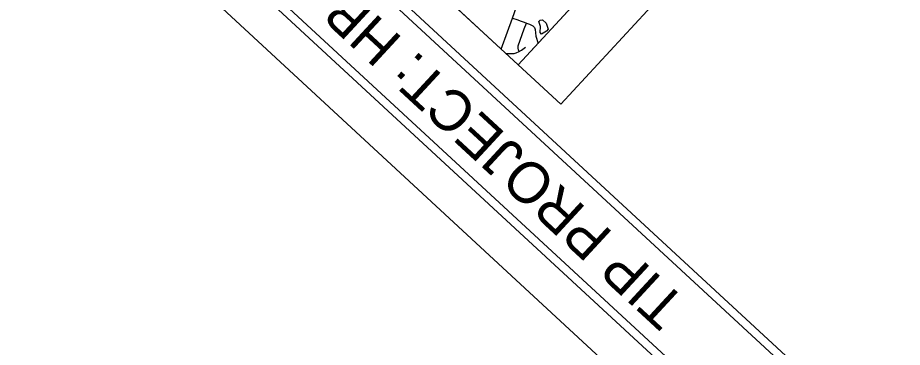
# Model space of a CAD drawing. Extents: x 1766669 to 1770980, y 998119 to 1002502.
# Drawn here: x 1766669 to 1767853, y 999053 to 999494 of the extents above; entities that cross this region are included whole.
import ezdxf

# ---------------------------------------------------------------- set-up
doc = ezdxf.new("R2010")
doc.units = 0
for name, color, linetype in [('Default', 7, 'Continuous'), ('Default Symbol CELL', 7, 'Continuous'), ('Exist DTM Breakline', 7, 'Continuous'), ('Exist DTM Crownline', 7, 'Continuous'), ('Exist Roads Soil', 7, 'Continuous'), ('PH Exist DTM Breakline', 7, 'Continuous')]:
    doc.layers.add(name, color=color, linetype=linetype)

msp = doc.modelspace()

# ---------------------------------------------------------------- linework, layer by layer
at = {"layer": 'Default'}
msp.add_lwpolyline([(1766911.4, 999825.8), (1767342.4, 1000292), (1767769.6, 999897.2), (1767338.6, 999431)], close=True, dxfattribs=at)
at = {"layer": 'Default Symbol CELL'}
for p, q in [((1767768.8, 999896.4), (1767338.6, 999431)), ((1767826.5, 999844.5), (1767395.6, 999378.3)), ((1768487.4, 998295.9), (1766841.5, 999817.2)), ((1768196.4, 998579.9), (1766849, 999825.3)), ((1767395.6, 999378.3), (1766911.4, 999825.8))]:
    msp.add_line(p, q, dxfattribs=at)
for points in [[(1766758.9, 999744.1), (1768420.8, 998207.8)], [(1766758.9, 999744), (1768420.9, 998207.7)], [(1766758.9, 999744), (1768420.9, 998207.7)], [(1766774.4, 999744.6), (1768420.3, 998223.3)]]:
    msp.add_lwpolyline(points, dxfattribs=at)
at = {"layer": 'Exist DTM Breakline'}
for points in [[(1767330.7, 999493.4), (1767336.8, 999491.4), (1767342.3, 999489.5), (1767346.3, 999487.9), (1767349.7, 999486.6)], [(1767339.7, 999448.5), (1767339.1, 999450.8), (1767338.5, 999453.2), (1767338.3, 999454.8), (1767338.4, 999456.3), (1767346.7, 999479), (1767349.7, 999486.6)], [(1767349.7, 999486.6), (1767353.5, 999485.2), (1767356.5, 999484.1), (1767357.9, 999483.2), (1767359.1, 999482.1), (1767360.2, 999480.8), (1767361.2, 999478.2), (1767362, 999469.2), (1767365.1, 999459.6)], [(1767322.2, 999446.2), (1767333.1, 999446), (1767334.4, 999446.5), (1767335.9, 999446.9), (1767339.7, 999448.5)], [(1767339.7, 999448.5), (1767343, 999450.3), (1767348.4, 999454.3)]]:
    msp.add_lwpolyline(points, dxfattribs=at)
at = {"layer": 'Exist DTM Crownline'}
msp.add_lwpolyline([(1767376.5, 999476.1), (1767369.8, 999472), (1767367.7, 999474), (1767368.5, 999482.2), (1767366.3, 999488.7), (1767367.7, 999490.8), (1767371, 999491.1), (1767375.9, 999486.5), (1767378.8, 999478.4), (1767376.5, 999476.1)], dxfattribs=at)
at = {"layer": 'Exist Roads Soil'}
for points in [[(1767330.7, 999493.4), (1767333.4, 999500.8), (1767336.2, 999508.6), (1767339.6, 999517.7), (1767340.1, 999519.6)], [(1767315.9, 999452), (1767324.2, 999474.9), (1767330.7, 999493.4)]]:
    msp.add_lwpolyline(points, dxfattribs=at)
at = {"layer": 'PH Exist DTM Breakline'}
msp.add_lwpolyline([(1766668.6, 999760.2), (1769205.6, 1002501.9), (1770979.8, 1000860.3), (1768442.7, 998118.5)], close=True, dxfattribs=at)

# ---------------------------------------------------------------- texts
at = {"layer": 'Default Symbol CELL'}
msp.add_text('TIP PROJECT: HB-0035', height=54.934, rotation=137.2512, dxfattribs=at).set_placement((1767566, 999113.5))

doc.saveas('drawing.dxf')
